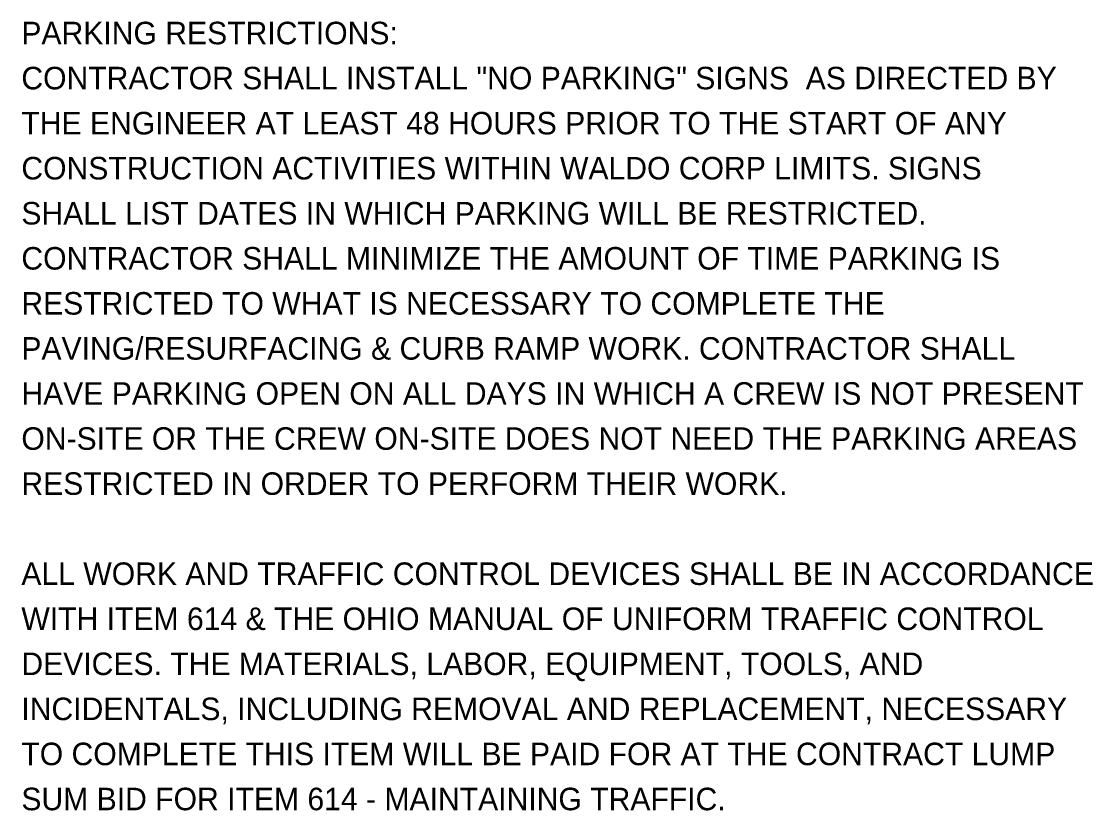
# Model space of a CAD drawing. Extents: x -23 to 32, y -58.1 to 21.1.
# Drawn here: x -22.98 to -16.32, y -21.72 to -16.82 of the extents above; entities that cross this region are included whole.
import ezdxf

# ---------------------------------------------------------------- set-up
doc = ezdxf.new("R2010")
doc.units = 0
doc.layers.add('SH_Text', color=7, linetype='Continuous')

msp = doc.modelspace()

# ---------------------------------------------------------------- texts
at = {"layer": 'SH_Text'}
for s, p in [('PARKING RESTRICTIONS:', (-22.9815, -16.9603)), ('CONTRACTOR SHALL INSTALL "NO PARKING" SIGNS  AS DIRECTED BY ', (-22.9815, -17.2403)), ('THE ENGINEER AT LEAST 48 HOURS PRIOR TO THE START OF ANY ', (-22.9815, -17.5203)), ('CONSTRUCTION ACTIVITIES WITHIN WALDO CORP LIMITS. SIGNS ', (-22.9815, -17.8003)), ('SHALL LIST DATES IN WHICH PARKING WILL BE RESTRICTED. ', (-22.9815, -18.0803)), ('CONTRACTOR SHALL MINIMIZE THE AMOUNT OF TIME PARKING IS ', (-22.9815, -18.3603)), ('RESTRICTED TO WHAT IS NECESSARY TO COMPLETE THE ', (-22.9815, -18.6403)), ('PAVING/RESURFACING & CURB RAMP WORK. CONTRACTOR SHALL ', (-22.9815, -18.9203)), ('HAVE PARKING OPEN ON ALL DAYS IN WHICH A CREW IS NOT PRESENT ', (-22.9815, -19.2003)), ('ON-SITE OR THE CREW ON-SITE DOES NOT NEED THE PARKING AREAS ', (-22.9815, -19.4803)), ('RESTRICTED IN ORDER TO PERFORM THEIR WORK.', (-22.9815, -19.7603)), ('ALL WORK AND TRAFFIC CONTROL DEVICES SHALL BE IN ACCORDANCE ', (-22.9815, -20.3203)), ('WITH ITEM 614 & THE OHIO MANUAL OF UNIFORM TRAFFIC CONTROL ', (-22.9815, -20.6003)), ('DEVICES. THE MATERIALS, LABOR, EQUIPMENT, TOOLS, AND ', (-22.9815, -20.8803)), ('INCIDENTALS, INCLUDING REMOVAL AND REPLACEMENT, NECESSARY ', (-22.9815, -21.1603)), ('TO COMPLETE THIS ITEM WILL BE PAID FOR AT THE CONTRACT LUMP ', (-22.9815, -21.4403)), ('SUM BID FOR ITEM 614 - MAINTAINING TRAFFIC.', (-22.9815, -21.7203))]:
    msp.add_text(s, height=0.14, dxfattribs=at).set_placement(p)

doc.saveas('drawing.dxf')
